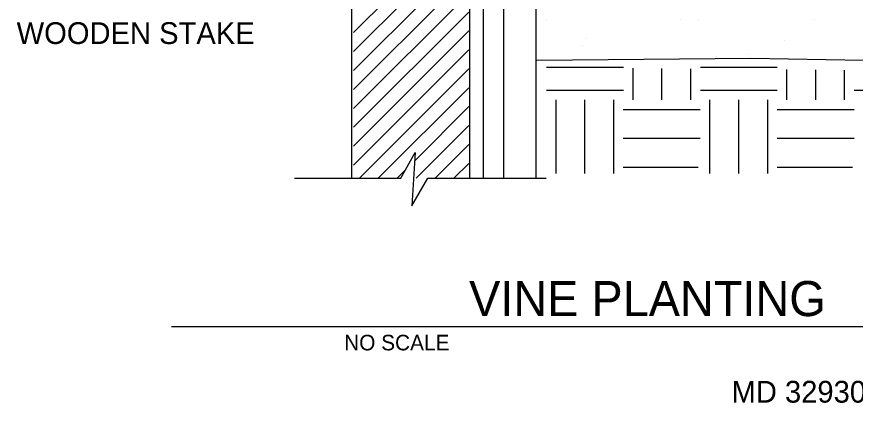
# Model space of a CAD drawing. Extents: x 10082 to 10257, y 10014 to 10069.
# Drawn here: x 10115.7 to 10142.62, y 10014.39 to 10027 of the extents above; entities that cross this region are included whole.
import ezdxf

# ---------------------------------------------------------------- set-up
doc = ezdxf.new("R2010")
doc.units = 0
for name, color, linetype in [('Default', 7, 'Continuous'), ('G-ANNO-CELL', 7, 'Continuous'), ('G-ANNO-TEXT', 7, 'Continuous'), ('G-DETL-GRID', 7, 'Continuous'), ('G-DETL-LINE', 7, 'Continuous'), ('G-DETL-OTLN', 7, 'Continuous'), ('G-DETL-PATT', 7, 'Continuous'), ('G-DETL-TEXT', 7, 'Continuous')]:
    doc.layers.add(name, color=color, linetype=linetype)

msp = doc.modelspace()

# ---------------------------------------------------------------- linework, layer by layer
at = {"layer": 'Default'}
msp.add_line((10132.711, 10026.895), (10132.711, 10026.895), dxfattribs=at)
at = {"layer": 'G-ANNO-TEXT'}
for p, q in [((10120.67, 10017.044), (10152.453, 10017.044)), ((10120.67, 10017.044), (10152.453, 10017.044)), ((10122.114, 10017.044), (10151.008, 10017.044)), ((10122.114, 10017.044), (10151.008, 10017.044))]:
    msp.add_line(p, q, dxfattribs=at)
at = {"layer": 'G-DETL-LINE'}
for p, q in [((10128.03, 10021.809), (10128.493, 10022.635)), ((10128.493, 10022.635), (10128.39, 10020.929)), ((10124.618, 10021.809), (10128.03, 10021.809)), ((10128.39, 10020.929), (10128.904, 10021.809)), ((10128.904, 10021.809), (10132.704, 10021.809))]:
    msp.add_line(p, q, dxfattribs=at)
for points in [[(10126.447, 10044.143), (10126.447, 10021.81)], [(10130.235, 10044.143), (10130.235, 10021.81)], [(10130.675, 10044.143), (10130.675, 10021.809)], [(10131.327, 10044.143), (10131.327, 10021.81)]]:
    msp.add_lwpolyline(points, dxfattribs=at)
at = {"layer": 'G-DETL-OTLN'}
for points in [[(10132.367, 10044.143), (10132.367, 10021.81)], [(10132.402, 10025.6), (10139.273, 10025.671), (10142.902, 10025.6), (10143.607, 10026.288), (10144.453, 10027.769), (10144.541, 10031.242), (10144.455, 10034.311)]]:
    msp.add_lwpolyline(points, dxfattribs=at)
at = {"layer": 'G-DETL-PATT'}
for p, q in [((10126.517, 10026.487), (10130.217, 10030.186)), ((10126.517, 10025.879), (10130.217, 10029.579)), ((10126.517, 10025.271), (10130.217, 10028.971)), ((10126.517, 10024.664), (10130.217, 10028.364)), ((10126.517, 10024.056), (10130.217, 10027.756)), ((10126.517, 10023.449), (10130.217, 10027.149)), ((10137.007, 10026.895), (10137.007, 10026.895)), ((10137.605, 10026.901), (10137.605, 10026.901)), ((10141.303, 10026.895), (10141.303, 10026.895)), ((10126.517, 10022.841), (10130.217, 10026.541)), ((10133.998, 10026.287), (10133.998, 10026.287)), ((10140.366, 10026.242), (10140.366, 10026.242)), ((10126.517, 10022.234), (10130.217, 10025.933)), ((10133.877, 10026.09), (10133.877, 10026.09)), ((10138.156, 10025.715), (10138.156, 10025.715)), ((10139.154, 10025.786), (10139.154, 10025.786)), ((10132.711, 10025.381), (10135.181, 10025.381)), ((10135.49, 10024.328), (10135.49, 10025.346)), ((10136.417, 10024.328), (10136.417, 10025.338)), ((10137.343, 10024.328), (10137.343, 10025.33)), ((10137.652, 10025.381), (10140.122, 10025.381)), ((10126.701, 10021.81), (10130.217, 10025.326)), ((10140.431, 10024.328), (10140.431, 10025.303)), ((10141.357, 10024.328), (10141.357, 10025.295)), ((10142.283, 10024.328), (10142.283, 10025.287)), ((10127.308, 10021.81), (10130.217, 10024.718)), ((10132.711, 10024.637), (10135.181, 10024.637)), ((10137.652, 10024.637), (10140.122, 10024.637)), ((10142.592, 10024.637), (10145.062, 10024.637)), ((10133.02, 10021.968), (10133.02, 10024.328)), ((10133.946, 10021.968), (10133.946, 10024.328)), ((10134.873, 10021.968), (10134.873, 10024.328)), ((10137.96, 10021.968), (10137.96, 10024.328)), ((10138.887, 10021.968), (10138.887, 10024.328)), ((10139.813, 10021.968), (10139.813, 10024.328)), ((10128.477, 10022.37), (10130.217, 10024.111)), ((10135.171, 10024.019), (10137.641, 10024.019)), ((10140.122, 10024.019), (10142.592, 10024.019)), ((10128.524, 10021.81), (10130.217, 10023.503)), ((10135.171, 10023.093), (10137.641, 10023.093)), ((10140.122, 10023.093), (10142.592, 10023.093)), ((10129.131, 10021.81), (10130.217, 10022.896)), ((10129.739, 10021.81), (10130.217, 10022.288)), ((10135.171, 10022.167), (10137.581, 10022.167)), ((10140.122, 10022.167), (10142.532, 10022.167)), ((10127.916, 10021.81), (10128.176, 10022.069))]:
    msp.add_line(p, q, dxfattribs=at)

# ---------------------------------------------------------------- texts
at = {"layer": 'G-ANNO-CELL'}
for s, height, p in [('NO SCALE', 0.5, (10126.212, 10016.282)), ('MD 329300 007 Vine Planting 7/27/18', 0.7, (10138.653, 10014.603))]:
    msp.add_text(s, height=height, dxfattribs=at).set_placement(p)
at = {"layer": 'G-DETL-GRID'}
msp.add_text('VINE PLANTING', height=1.125, dxfattribs=at).set_placement((10130.224, 10017.383))
at = {"layer": 'G-DETL-TEXT'}
msp.add_text('WOODEN STAKE', height=0.7, dxfattribs=at).set_placement((10115.694, 10026.122))

doc.saveas('drawing.dxf')
